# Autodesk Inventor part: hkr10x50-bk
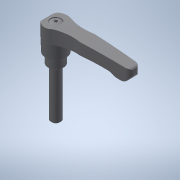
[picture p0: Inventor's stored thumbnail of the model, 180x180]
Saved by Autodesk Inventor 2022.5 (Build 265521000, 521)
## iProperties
Created: 2017-09
Part Number: hkr10x50-bk
Material: 一般
Document SubType Name: Modeling
Designer: imaocorp
Density: 1 g/cm^3
Appearance: 既定
Author: imaocorp
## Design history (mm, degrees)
node "hkr10x50-bk.x_t1"
node "hkr10x50-bk"
node "Base1"
